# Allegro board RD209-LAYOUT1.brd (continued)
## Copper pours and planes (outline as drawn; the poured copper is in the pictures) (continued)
LV6 on TOP: 104.77,69.85 104.77,78.1 110.49,78.1 110.49,69.85
LV6 on CONDUCTIVE2: 80.08,40.64 80.03,40.66 80.01,40.72 80.01,73.58 80.03,73.64 80.08,73.66 104.77,73.66 104.77,78.03 104.8,78.08 104.85,78.1 110.41,78.1 110.47,78.08 110.49,78.03 110.49,69.92 110.47,69.87 110.41,69.85 87.63,69.85 87.63,46.36 93.21,46.36 93.29,46.29 93.23,46.21 93.34,45.22 93.46,46.21 93.4,46.29 93.48,46.36 97.71,46.36 97.77,46.33 97.79,46.28 97.79,40.72 97.77,40.66 97.71,40.64
LV7 on TOP: 141.61,69.85 141.61,78.1 147.32,78.1 147.32,69.85
LV7 on TOP: 116.84,52.71 116.84,53.98 124.46,53.98 124.46,52.71
LV7 on TOP: 132.08,45.09 132.08,46.36 134.62,46.36 134.62,45.09
LV7 on CONDUCTIVE2: 116.91,40.64 116.86,40.66 116.84,40.72 116.84,73.58 116.86,73.64 116.91,73.66 141.61,73.66 141.61,78.03 141.63,78.08 141.68,78.1 147.25,78.1 147.3,78.08 147.32,78.03 147.32,69.92 147.3,69.87 147.25,69.85 124.46,69.85 124.46,46.36 130.04,46.36 130.12,46.29 130.06,46.21 130.18,45.22 130.29,46.21 130.23,46.29 130.31,46.36 134.55,46.36 134.6,46.33 134.62,46.28 134.62,40.72 134.6,40.66 134.55,40.64
N_8 on TOP: 15.24,120.65 15.24,129.54 29.21,129.54 29.21,120.65
N_9 on TOP: 29.84,118.11 29.84,123.66 30.51,123.66 30.64,123.69 30.73,123.78 30.98,123.78 31.02,123.83 35.56,123.83 35.56,118.11
N_54 on TOP: 53.98,5.71 53.98,9.53 60.33,9.53 60.33,5.71
N_159 on TOP: 138.11,79.38 138.11,83.19 147.32,83.19 147.32,79.38
N_208 on TOP: 53.98,104.14 53.98,109.85 60.33,109.85 60.33,107.95 62.23,106.05 62.23,105.41 60.96,105.41 60.96,106.05 58.42,106.05 58.42,104.14
N_209 on TOP: 101.28,79.38 101.28,83.19 110.49,83.19 110.49,79.38
N_214 on TOP: 64.45,135.26 64.45,139.06 73.66,139.06 73.66,135.26
N_217 on TOP: 64.45,79.38 64.45,83.19 73.66,83.19 73.66,79.38
N_218 on TOP: 101.28,135.26 101.28,139.06 110.49,139.06 110.49,135.26
N_219 on TOP: 90.8,104.14 90.8,109.85 97.16,109.85 97.16,107.95 99.06,106.05 99.06,105.41 97.79,105.41 97.79,106.05 95.25,106.05 95.25,104.14
N_220 on TOP: 27.62,135.26 27.62,139.06 36.83,139.06 36.83,135.26
N_221 on TOP: 17.14,104.14 17.14,109.85 23.5,109.85 23.5,107.95 25.4,106.05 25.4,105.41 24.13,105.41 24.13,106.05 21.59,106.05 21.59,104.14
N_222 on TOP: 127.63,104.14 127.63,109.85 133.99,109.85 133.99,107.95 135.89,106.05 135.89,105.41 134.62,105.41 134.62,106.05 132.08,106.05 132.08,104.14
N_223 on TOP: 53.98,48.26 53.98,53.98 60.33,53.98 60.33,52.07 62.23,50.17 62.23,49.53 60.96,49.53 60.96,50.17 58.42,50.17 58.42,48.26
N_224 on TOP: 90.8,48.26 90.8,53.98 97.16,53.98 97.16,52.07 99.06,50.17 99.06,49.53 97.79,49.53 97.79,50.17 95.25,50.17 95.25,48.26
N_225 on TOP: 127.63,48.26 127.63,53.98 133.99,53.98 133.99,52.07 135.89,50.17 135.89,49.53 134.62,49.53 134.62,50.17 132.08,50.17 132.08,48.26
N_235 on TOP: 26.04,24.77 26.04,31.11 24.77,31.11 24.77,33.49 25.43,33.49 25.56,33.53 25.66,33.63 25.67,33.66 26.04,33.66 26.04,36.83 31.11,36.83 31.11,32.55 30.45,32.55 30.32,32.51 30.22,32.41 30.21,32.38 29.84,32.38 29.84,24.77
N_256 on TOP: 52.07,120.65 52.07,129.54 66.04,129.54 66.04,120.65
N_257 on TOP: 66.67,118.11 66.67,123.66 67.34,123.66 67.47,123.69 67.56,123.78 67.81,123.78 67.85,123.83 72.39,123.83 72.39,118.11
N_271 on TOP: 88.9,120.65 88.9,129.54 102.87,129.54 102.87,120.65
N_272 on TOP: 103.5,118.11 103.5,123.66 104.17,123.66 104.3,123.69 104.39,123.78 104.64,123.78 104.68,123.83 109.22,123.83 109.22,118.11
N_286 on TOP: 125.73,120.65 125.73,129.54 139.7,129.54 139.7,120.65
N_287 on TOP: 140.34,118.11 140.34,123.66 141,123.66 141.13,123.69 141.22,123.78 141.47,123.78 141.51,123.83 146.05,123.83 146.05,118.11
N_292 on TOP: 138.11,135.26 138.11,139.06 147.32,139.06 147.32,135.26
N_301 on TOP: 52.07,64.77 52.07,73.66 66.04,73.66 66.04,64.77
N_302 on TOP: 66.67,62.23 66.67,67.78 67.34,67.78 67.47,67.81 67.56,67.9 67.81,67.9 67.85,67.94 72.39,67.94 72.39,62.23
N_316 on TOP: 88.9,64.77 88.9,73.66 102.87,73.66 102.87,64.77
N_317 on TOP: 103.5,62.23 103.5,67.78 104.17,67.78 104.3,67.81 104.39,67.9 104.64,67.9 104.68,67.94 109.22,67.94 109.22,62.23
N_331 on TOP: 125.73,64.77 125.73,73.66 139.7,73.66 139.7,64.77
N_332 on TOP: 140.34,62.23 140.34,67.78 141,67.78 141.13,67.81 141.22,67.9 141.47,67.9 141.51,67.94 146.05,67.94 146.05,62.23

Small or netless copper shapes (teardrops, artwork), in the pictures only: 6 on CONDUCTIVE2, 2 on CONDUCTIVE3

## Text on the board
Ref Des/Silkscreen Top: 1 | ZD55 | U1 | ZD56 | ZD59 | U8 | U5 | ZD60 | ZD57 | U9 | U6 | ZD58 | ZD61 | U10 | U7 | C2 | C68 | C28 | C49 | C35 | C56 | C42 | C63 | C6 | C5 | C7 | C8 | C31 | C52 | C27 | C48 | C30 | C51 | C38 | C59 | C34 | C55 | C58 | C37 | C45 | C66 | C41 | C62 | C44 | C65 | C18 | C3 | C32 | C19 | C76 | C75 | C46 | C39 | C72 | C67 | C60 | C53 | C74 | C73 | C1 | C4 | C21 | C29 | C50 | C70 | C69 | C26 | C47 | C9 | C12 | C71 | C36 | C57 | C33 | C54 | C13 | C10 | C64 | C43 | C40 | C61 | C14 | C11 | D52 | R119 | ZD44 | R129 | R128 | U3 | ZD45 | R126 | ZD46 | R22 | R130 | SW1 | R2 | R3 | ZD47 | R185 | IC4 | R121 | R188 | P24 | R82 | R37 | P23 | Q81 | R160 | R134 | R161 | R133 | CON1 | R123 | R190 | R52 | R97 | R143 | R169 | R170 | R142 | R186 | R192 | R112 | R67 | R152 | R151 | R179 | R178 | CON10 | CON2 | D1 | R118 | Q73 | R4 | CON9 | R23 | R127 | R9 | Q1 | R7 | R8 | R1 | R6 | CON3 | CON6 | SJ9 | D48 | D51 | R120 | R187 | R139 | R166 | R38 | R83 | R138 | R165 | Q75 | Q78 | SJ8 | R163 | R136 | R137 | R164 | R162 | R135 | CON4 | CON7 | D49 | R189 | R122 | R175 | R148 | R98 | R53 | R174 | R147 | Q76 | Q79 | R145 | R172 | R146 | R173 | R171 | R144 | CON5 | CON8 | D53 | D50 | R124 | R191 | R184 | R157 | R113 | R68 | R183 | R156 | Q77 | Q80 | R154 | R181 | R155 | R182 | R180 | R153 | SJ1 | L1 | R24 | Q2 | R125 | R5 | Q74 | SJ2 | SJ5 | L2 | L5 | R39 | R84 | Q12 | Q42 | R132 | R159 | R158 | R131 | SJ3 | SJ6 | L6 | L3 | R99 | R54 | Q22 | Q52 | R141 | R168 | R167 | R140 | SJ4 | SJ7 | L7 | L4 | R69 | R114 | Q62 | Q32 | R177 | R150 | R149 | R176
PAGE_OUTLINE: 1
SYMBOL-2-TOP: 1
